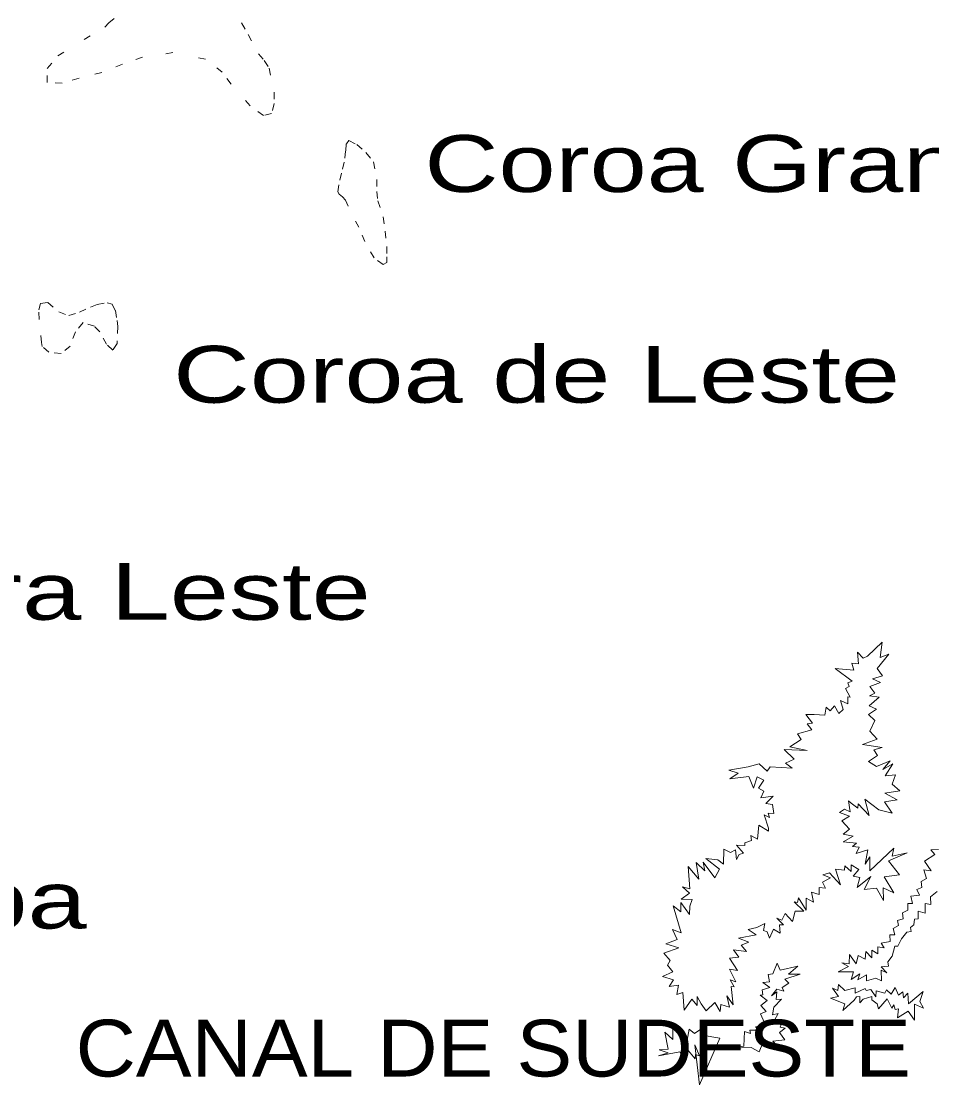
# Model space of a CAD drawing. Extents: x 47169 to 972804, y 7447977 to 9608469.
# Drawn here: x 487096 to 497530, y 8032561 to 8044744 of the extents above; entities that cross this region are included whole.
import ezdxf

# ---------------------------------------------------------------- set-up
doc = ezdxf.new("R2010")
doc.units = 0
doc.header["$LTSCALE"] = 270
doc.linetypes.add('DOTTED', pattern=[1.5, 0.3, -1.2])
doc.layers.add('1', color=7, linetype='Continuous', lineweight=13)
doc.layers.add('3', color=7, linetype='Continuous')

msp = doc.modelspace()

# ---------------------------------------------------------------- linework, layer by layer
at = {"layer": '1', "linetype": 'DOTTED'}
msp.add_lwpolyline([(489519.3, 8044936), (489621.2, 8044725.9), (489695.5, 8044590.9), (489815.5, 8044369.7), (489881.3, 8044293.4), (489937.5, 8044207.2), (489993.9, 8043932.8), (489996.1, 8043801.2), (489965.4, 8043686.1), (489871, 8043663.9), (489718.2, 8043775.6), (489501.7, 8044024.4), (489399.9, 8044161.5), (489206.8, 8044310.8), (488834.5, 8044384.7), (488486.7, 8044331.4), (488256.6, 8044252.7), (488018, 8044155.2), (487758.2, 8044092), (487564.2, 8044035.4), (487391.3, 8044043.1), (487394.4, 8044203.5), (487516.3, 8044346.3), (487816.3, 8044534.5), (488052.7, 8044676.3), (488099.4, 8044725), (488244.6, 8044841.3)], dxfattribs=at)
for points in [[(491170.5, 8042794.9), (491183.2, 8042685.4), (491243.8, 8042505.1), (491267.2, 8042340.3), (491285.3, 8042164.4), (491285.3, 8042044.9), (491284.3, 8041979.6), (491241.9, 8041956.4), (491140, 8042032.7), (491032.9, 8042220.7), (490963.9, 8042383.3), (490843.9, 8042624.4), (490813.1, 8042695.2), (490778.1, 8042733.9), (490739.9, 8042761.5), (490724, 8042789.2), (490745.2, 8042924.2), (490778, 8043049.2), (490805.5, 8043175.4), (490813.9, 8043259.4), (490821.3, 8043341.3), (490848.9, 8043376.7), (490943.3, 8043331.4), (491045.1, 8043239.6), (491134.3, 8043132.4), (491172.5, 8042932.1)], [(487300.8, 8041329.2), (487298.6, 8041438.7), (487316.6, 8041509.5), (487402.5, 8041522.8), (487525.5, 8041413.4), (487642.2, 8041372.5), (487762, 8041411.3), (487891.3, 8041468.9), (487967.7, 8041497.7), (488080, 8041519.9), (488136.2, 8041502.2), (488174.5, 8041429.3), (488194.7, 8041314.2), (488202.2, 8041248.9), (488196.9, 8041083), (488194.8, 8041053.1), (488144, 8040976.7), (488072.9, 8041043.1), (487996.5, 8041186.9), (487934.9, 8041251), (487805.5, 8041291.8), (487716.5, 8041184.5), (487657.3, 8041021.8), (487553.4, 8040937.7), (487413.4, 8040953.1), (487337, 8041017.2), (487326.4, 8041062.5)]]:
    msp.add_lwpolyline(points, close=True, dxfattribs=at)
at = {"layer": '1'}
for points in [[(495435, 8036091.9), (495215.5, 8036064.2), (495309.9, 8036130.6), (495204.9, 8036163.7), (495424.3, 8036201.4), (495551.5, 8036239.1), (495642.7, 8036152.8), (495678.8, 8036201.5), (495931.1, 8036189.4), (495854.7, 8036244.7), (495953.3, 8036290), (495838.8, 8036401.8), (496103.8, 8036389.6), (495902.4, 8036432.7), (496034.9, 8036514.6), (495991.4, 8036579.9), (496154.7, 8036628.6), (496103.8, 8036695), (496162.1, 8036705), (496085.7, 8036801.2), (496182.2, 8036803.4), (496305.2, 8036793.5), (496320, 8036885.3), (496365.6, 8036844.4), (496414.3, 8036903), (496465.2, 8036814.5), (496516.1, 8036859.9), (496483.2, 8036961.7), (496567, 8036923), (496567, 8037004.9), (496594.5, 8037002.6), (496541.5, 8037101.1), (496585, 8037124.3), (496566.9, 8037165.3), (496617.8, 8037183), (496424.9, 8037327.9), (496635.8, 8037309.1), (496612.5, 8037391), (496692, 8037383.2), (496679.3, 8037514.9), (496745, 8037449.6), (496793.8, 8037469.5), (496961.2, 8037632.2), (496939, 8037454.1), (497037.6, 8037495), (496905.1, 8037328), (496964.5, 8037243.9), (496852.1, 8037212.9), (496943.3, 8037169.8), (496821.4, 8037124.4), (496877.6, 8037048), (496816.1, 8037017.1), (496926.4, 8037001.6), (496814, 8036903.1), (496895.6, 8036864.4), (496803.4, 8036803.5), (496877.6, 8036735), (496821.5, 8036613.2), (496905.2, 8036519.2), (496737.7, 8036460.6), (496961.4, 8036423), (496867.1, 8036399.7), (496908.4, 8036331.1), (496806.7, 8036262.5), (496895.7, 8036207.2), (497052.6, 8036272.5), (496968.9, 8036170.7), (497083.4, 8036239.3), (496997.5, 8036099.9), (497114.1, 8036113.2), (497076, 8036003.7), (497162.9, 8035927.4), (496992.2, 8035901.9), (497134.3, 8035823.4), (496989.1, 8035802.3), (497076, 8035672.9), (496923.4, 8035711.6), (496763.3, 8035831), (496814.2, 8035647.4), (496687, 8035780.1), (496683.8, 8035729.2), (496607.5, 8035787.9), (496574.6, 8035813.3), (496594.8, 8035688.3), (496529, 8035719.3), (496472.9, 8035680.5), (496587.3, 8035639.6), (496500.4, 8035584.3), (496587.4, 8035490.3), (496513.2, 8035431.6), (496627.7, 8035408.4), (496516.4, 8035343.1), (496665.8, 8035329.9), (496623.5, 8035288.9), (496696.6, 8035281.2), (496663.8, 8035210.4), (496798.4, 8035253.5), (496767.7, 8035088.7), (496818.5, 8035172.8), (496818.5, 8035012.4), (497096.2, 8035271.3)], [(495755.5, 8034471.2), (495831.8, 8034392.6), (495785.2, 8034392.6), (495793.7, 8034298.6), (495717.3, 8034343.9), (495670.7, 8034242.1), (495645.2, 8034312.9), (495602.8, 8034328.4), (495615.5, 8034407), (495526.5, 8034361.6), (495424.8, 8034338.3), (495518.1, 8034277.5), (495314.5, 8034239.8), (495434.3, 8034193.4), (495345.3, 8034161.3), (495406.8, 8034089.4), (495256.3, 8034107), (495319.9, 8034024.1), (495212.8, 8034013), (495301.9, 8033868.1), (495212.9, 8033883.5), (495283.9, 8033742), (495220.3, 8033761.9), (495263.8, 8033683.3), (495230.9, 8033687.7), (495254.3, 8033477.5), (495180.1, 8033581.5), (495210.9, 8033448.8), (495114.4, 8033481.9), (495103.8, 8033398.9), (495045.5, 8033502.9), (494943.8, 8033408.9), (494887.6, 8033487.4), (494842, 8033571.5), (494842, 8033469.7), (494780.5, 8033542.7), (494691.5, 8033416.5), (494678.7, 8033616.8), (494609.8, 8033596.9), (494627.8, 8033700.9), (494520.8, 8033685.3), (494571.6, 8033761.7), (494444.4, 8033802.6), (494562.1, 8033855.7), (494500.6, 8033929.8), (494531.3, 8033985.2), (494460.2, 8034067), (494630.9, 8034127.9), (494482.5, 8034175.4), (494612.9, 8034226.4), (494558.8, 8034338.1), (494658.4, 8034302.7), (494567.2, 8034610.3), (494653, 8034541.7), (494653, 8034649), (494754.8, 8034511.8), (494758, 8034608.1), (494783.4, 8034682.2), (494658.3, 8034688.8), (494752.6, 8034757.5), (494673.1, 8034829.3), (494757.9, 8034803.9), (494737.7, 8035062.8), (494859.6, 8034917.9), (494831, 8035106), (494930.6, 8035009.8), (494910.5, 8035111.5), (495043, 8034933.4), (495098.1, 8035029.7), (494941.2, 8035151.4), (495078, 8035137), (495144.7, 8035088.4), (495148.9, 8035258.7), (495223.2, 8035220), (495281.4, 8035253.2), (495292.1, 8035141.5), (495322.8, 8035200.1), (495373.7, 8035213.4), (495294.2, 8035307.5), (495388.5, 8035301.9), (495388.5, 8035331.8), (495462.7, 8035357.3), (495455.3, 8035415.9), (495533.7, 8035372.8), (495548.5, 8035533.2), (495660.9, 8035464.6), (495660.9, 8035502.2), (495610, 8035652.7), (495671.5, 8035621.7), (495653.4, 8035672.6), (495719.2, 8035668.2), (495706.4, 8035770), (495630.1, 8035782.2), (495711.7, 8035868.5), (495569.7, 8035848.5), (495604.6, 8035924.9), (495544.2, 8035960.2), (495604.6, 8036048.8), (495528.2, 8036087.5), (495485.9, 8035960.2), (495435, 8036091.9)], [(497096.2, 8035271.3), (497076.1, 8035180.6), (497248.9, 8035218.2), (497034.8, 8035126.3), (497159.9, 8034967), (496983.9, 8034943.8), (497094.2, 8034757.9), (496971.2, 8034816.5), (496976.5, 8034671.6), (496894.9, 8034812.1), (496755, 8034796.6), (496831.3, 8034946), (496673.3, 8034822), (496704.1, 8034933.8), (496630.9, 8034951.5), (496694.5, 8035027.8), (496607.6, 8035080.9), (496607.6, 8035002.4), (496533.4, 8035068.7), (496531.3, 8035017.8), (496427.4, 8035030), (496485.7, 8034851.9), (496358.5, 8034989), (496282.2, 8034966.9), (496368, 8034931.5), (496276.9, 8034882.8), (496312.9, 8034812), (496240.9, 8034822), (496240.9, 8034740.1), (496151.8, 8034768.8), (496175.2, 8034653.8), (496091.4, 8034700.2), (496091.5, 8034559.7), (496002.4, 8034702.4), (495991.8, 8034649.3), (495953.6, 8034656), (496062.8, 8034549.8), (495966.4, 8034549.7), (495933.5, 8034430.2), (495849.8, 8034522.1), (495811.6, 8034447.9), (495755.5, 8034471.2)], [(497592.4, 8034773.5), (497516.1, 8034712.6), (497518.2, 8034626.3), (497452.5, 8034638.5), (497452.5, 8034526.8), (497374, 8034547.8), (497374.1, 8034461.5), (497330.6, 8034458.2), (497323.2, 8034391.8), (497287.2, 8034364.1), (497294.6, 8034316.5), (497243.7, 8034311), (497182.2, 8034232.4), (497139.9, 8034150.5), (497105.9, 8034150.5), (497076.3, 8034034.4), (497027.5, 8033970.2), (497032.8, 8033919.3), (496949.1, 8033911.5), (497016.9, 8033843), (496951.2, 8033873.9), (496953.4, 8033752.2), (496887.6, 8033782.1), (496782.7, 8033752.2), (496782.7, 8033820.8), (496684.1, 8033762.2), (496706.4, 8033833), (496604.6, 8033766.6), (496633.2, 8033854), (496457.3, 8033853.9), (496574.9, 8033917), (496498.6, 8033958), (496582.3, 8033948), (496587.6, 8034052), (496664, 8033948), (496686.2, 8034042.1), (496767.8, 8033998.9), (496773.1, 8034087.4), (496842, 8034016.6), (496842, 8034102.9), (496913, 8034059.8), (496913, 8034140.6), (496984, 8034128.4), (496949, 8034183.7), (497052.9, 8034201.4), (497047.6, 8034280), (497105.9, 8034280), (497085.8, 8034351.9), (497147.2, 8034387.3), (497136.6, 8034442.6), (497203.4, 8034461.5), (497196, 8034532.3), (497254.3, 8034559.9), (497254.3, 8034638.5), (497310.4, 8034638.5), (497289.2, 8034720.4), (497388.9, 8034732.5), (497358.1, 8034796.7), (497416.4, 8034822.2), (497406.9, 8034890.7), (497470.5, 8034923.9), (497439.7, 8035022.4), (497523.5, 8035012.5), (497447.1, 8035124.2), (497566.9, 8035198.3), (497519.2, 8035253.6), (497608.2, 8035255.9)]]:
    msp.add_lwpolyline(points, dxfattribs=at)
for points in [[(495236.4, 8032979.7), (495376.3, 8033001.8), (495385.8, 8033172.2), (495452.6, 8033146.8), (495445.2, 8033187.7), (495559.6, 8033187.7), (495510.9, 8033223.1), (495563.9, 8033236.4), (495559.6, 8033260.8), (495612.6, 8033271.8), (495567, 8033373.6), (495632.7, 8033399.1), (495572.3, 8033469.9), (495645.4, 8033525.2), (495561.7, 8033589.3), (495592.4, 8033591.6), (495585, 8033648), (495674, 8033675.7), (495594.5, 8033731), (495670.8, 8033742), (495653.8, 8033825), (495709, 8033830.6), (495759.8, 8033952.3), (495793.7, 8033873.7), (495994.1, 8033919.1), (495887, 8033828.4), (496022.7, 8033828.4), (495844.6, 8033769.7), (495890.2, 8033723.3), (495816, 8033675.7), (495836.2, 8033632.5), (495755.6, 8033658), (495694.2, 8033581.6), (495755.6, 8033627), (495745, 8033536.3), (495806.5, 8033542.9), (495719.6, 8033448.9), (495703.8, 8033362.6), (495770.5, 8033375.9), (495729.2, 8033299.5), (495821.4, 8033299.5), (495792.8, 8033221), (495849, 8033207.7), (495785.4, 8033160.1), (495846.9, 8033076), (495707, 8033060.5), (495745.2, 8033017.4), (495592.5, 8033042.8), (495551.2, 8032938.8), (495462.2, 8032989.7)], [(497258.7, 8033403.8), (497136.8, 8033327.4), (497147.4, 8033431.4), (497111.3, 8033421.5), (497096.5, 8033477.9), (497073.2, 8033439.2), (497017, 8033546.5), (496918.4, 8033431.4), (496902.5, 8033487.8), (496844.2, 8033535.4), (496844.2, 8033571.9), (496744.6, 8033543.1), (496706.4, 8033497.7), (496706.4, 8033571.9), (496666.1, 8033568.5), (496640.7, 8033528.7), (496511.4, 8033411.4), (496533.7, 8033487.8), (496370.4, 8033554.1), (496462.6, 8033571.8), (496393.7, 8033668.1), (496455.2, 8033642.6), (496462.6, 8033709), (496533.6, 8033642.6), (496651.3, 8033670.3), (496651.3, 8033611.7), (496767.9, 8033662.6), (496778.5, 8033642.7), (496833.6, 8033652.7), (496887.7, 8033566.4), (496893, 8033637.2), (496991.5, 8033609.5), (497012.7, 8033648.2), (497065.7, 8033597.4), (497111.3, 8033675.9), (497147.4, 8033586.3), (497198.2, 8033627.3), (497205.7, 8033558.7), (497254.4, 8033611.8), (497264, 8033487.9), (497432.5, 8033629.5), (497394.3, 8033515.5), (497436.7, 8033439.2), (497332.9, 8033482.4), (497330.8, 8033299.8)], [(494564.4, 8033232.9), (494648.1, 8033111.2), (494693.7, 8033138.9), (494727.6, 8033073.6), (494749.9, 8033199.7), (494811.3, 8033146.6), (494905.7, 8033213), (494900.4, 8033128.9), (495100.7, 8033093.6), (494869.8, 8032561.4), (494813.5, 8033019.4), (494869.7, 8032892.2), (494820.9, 8032907.7), (494818.8, 8032856.8), (494722.4, 8032971.8), (494660.9, 8032960.7), (494673.6, 8032882.2), (494642.9, 8032936.4), (494399.1, 8032892), (494508.3, 8032925.3), (494404.4, 8032961.8), (494510.4, 8032968.4), (494470, 8033162), (494561.2, 8033080.2)]]:
    msp.add_lwpolyline(points, close=True, dxfattribs=at)

# ---------------------------------------------------------------- texts
at = {"layer": '3'}
for s, height, width, p in [('Coroa Grande', 650.9, 1.35, (491716.6, 8042788.5)), ('Coroa de Leste', 650.8, 1.4, (488835.7, 8040374.2)), ('Barra Leste', 650.7, 1.4, (484804.1, 8037887.8)), ('Barra do Tomba', 650.6, 1.4, (479044.7, 8034351)), ('CANAL DE SUDESTE', 650.6, 1.1, (487718.6, 8032655.6))]:
    msp.add_text(s, height=height, dxfattribs=dict(at, width=width)).set_placement(p)

doc.saveas('drawing.dxf')
